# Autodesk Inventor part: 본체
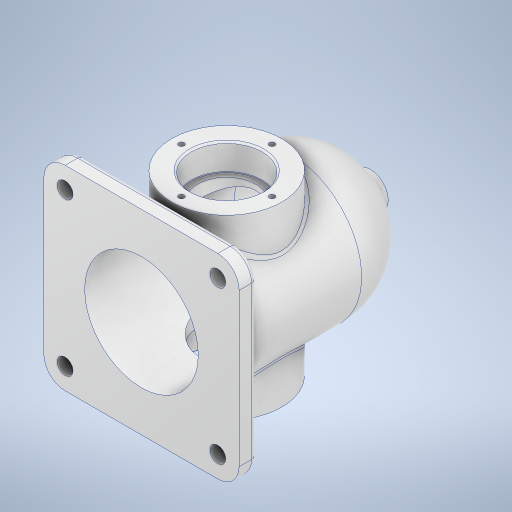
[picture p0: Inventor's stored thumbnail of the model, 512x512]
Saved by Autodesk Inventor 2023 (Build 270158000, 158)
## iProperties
Created: 2025-04
Part Number: 본체
Material: 알루미늄 6061
Document SubType Name: Modeling
Designer: ADMIN_PC
Density: 2.7 g/cm^3
Appearance: 알루미늄 - 평지
Mass: 865.906 g
Surface Area: 800.755 cm^2
Volume: 320.706 cm^3
Author: ADMIN_PC
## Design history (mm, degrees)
sketch "스케치1"
  geometry: L1 (-55, -55)-(55, -55); L2 (55, -55)-(55, 55); L3 (55, 55)-(-55, 55); L4 (-55, 55)-(-55, -55); L5 (-55, -55)-(55, 55); L6 (55, -55)-(-55, 55); 1 further point
  constraints: 12 end point, 2 midpoint, 2 parallel, 1 horizontal, 1 perpendicular
  dimensions: "d0" = 110 distance of L2.end L3.end; "d1" = 110 distance of L1.end L2.end
extrude "돌출1" new body sketch "스케치1" distance "d2" = 10; taper "d3" = 0 deg
fillet "모깎기1" dims "d4" = 12
sketch "스케치2"
  geometry: C1 r 40 at (0, 0); 1 further point
  constraints: 1 centre point, 1 coincident
  dimensions: "d5" = 80 diameter of C1
extrude "돌출2" join sketch "스케치2" distance "d6" = 74; taper "d7" = 0 deg
sketch "스케치3"
  geometry: L1 (-40, -74)-(40, -74) reference; L2 (0, -138.8)-(0, 34.8) reference; A1 r 40 centre (0, -74) between (-40, -74) and (0, -114); 2 further points
  constraints: 2 end point, 2 point on circle, 1 centre point, 1 midpoint, 1 point on line
revolve "회전1" sketch "스케치3" stored, may be unused: angle "d9" = 90 deg
sketch "스케치4"
  geometry: C1 r 32 at (0, 0); 1 further point
  constraints: 1 centre point, 1 coincident
  dimensions: "d10" = 64 diameter of C1
extrude "돌출3" cut sketch "스케치4" distance "d11" = 84; taper "d12" = 0 deg
sketch "스케치5"
  geometry: L1 (-32, -74)-(32, -74) reference; L2 (0, -138.8)-(0, 34.8) reference; A1 r 32 centre (0, -74) between (-32, -74) and (0, -106); 2 further points
  constraints: 2 point on circle, 1 centre point, 1 end point, 1 midpoint, 1 point on line
revolve "회전2" sketch "스케치5" stored, may be unused: angle "d13" = 90 deg
node "작업 평면2"
sketch "스케치6"
  geometry: L1 (-43, 10)-(43, 10) reference; L2 (0, 10)-(0, -38); C1 r 31 at (0, -38); 1 further point
  constraints: 2 end point, 1 centre point, 1 coincident, 1 midpoint, 1 vertical
  dimensions: "d15" = 48 distance of L2.start L2.end; "d16" = 62 diameter of C1
extrude "돌출4" join sketch "스케치6" stored distance "d17" = 84; taper "d18" = 0 deg
sketch "스케치7"
  geometry: C1 r 20 at (0, 0); 1 further point
  constraints: 1 centre point
  dimensions: "d19" = 40 diameter of C1
extrude "돌출5" cut sketch "스케치7" distance "d20" = 15; taper "d21" = 0 deg
sketch "스케치8"
  geometry: C1 r 16.5 at (0, 0); 1 further point
  constraints: 1 centre point
  dimensions: "d22" = 33 diameter of C1
extrude "돌출6" cut sketch "스케치8" extent not by distance; stored distance "d23" = 0; taper "d24" = 0 deg
sketch "스케치9"
  geometry: L1 (-43, -43)-(43, -43); L2 (43, -43)-(43, 43); L3 (43, 43)-(-43, 43); L4 (-43, 43)-(-43, -43); L5 (-43, -43)-(43, 43); L6 (43, -43)-(-43, 43); 5 further points
  constraints: 12 end point, 4 coincident, 2 midpoint, 2 parallel, 1 horizontal, 1 perpendicular
  dimensions: "d25" = 86 distance of L2.end L3.end; "d26" = 86 distance of L1.end L2.end
hole "구멍1" sketch "스케치9" at (-43, 43), (-43, -43), (43, -43), (43, 43) diameter "d27" = 9; stored, may be unused: countersink angle "d31" = 90 deg, drill point angle "d33" = 0 deg; dims "d28" = 12, "d29" = 4, "d30" = 2, "d32" = 17.1
sketch "스케치10" dims "d34" = 51
  geometry: L1 (0, 100.8)-(0, -72.8) reference; 3 further points
  constraints: 1 point on line, 1 vertical alignment, 2 other
hole "구멍2" sketch "스케치10" at (0, 25.5) diameter "d35" = 3.242; stored, may be unused: countersink angle "d39" = 90 deg, drill point angle "d41" = 118 deg; dims "d36" = 8, "d37" = 4, "d38" = 2, "d40" = 10
node "작업 평면3"
sketch "스케치11"
  geometry: C1 r 10 at (0, 0); 1 further point
  constraints: 1 centre point, 1 coincident
  dimensions: "d46" = 20 diameter of C1
extrude "돌출7" join sketch "스케치11" stored distance "d47" = 10; taper "d48" = 0 deg
sketch "스케치12"
  geometry: 2 further points
  constraints: 1 coincident
hole "구멍3" sketch "스케치12" at (0, 0) diameter "d49" = 5.1881; stored, may be unused: countersink angle "d53" = 90 deg, drill point angle "d55" = 0 deg; dims "d50" = 12, "d51" = 4, "d52" = 2, "d54" = 16
chamfer "모따기1" distance "d56" = 1; stored, may be unused: second distance "d57" = 2, angle "d58" = 45 deg
fillet "모깎기2" dims "d59" = 0.3
fillet "모깎기3" dims "d60" = 3
fillet "모깎기4" dims "d61" = 3
node "작업 평면4"
sketch "스케치13"
  geometry: L1 (-43, 10)-(43, 10) reference; L2 (-50, -7)-(-50, -69) reference; 2 further points
  constraints: 1 other
  dimensions: "d63" = 30 distance from line of L1 point (0, -20); "d64" = 50 distance from line of L2 point (0, -20)
feature "엠보싱1" sketch "스케치13" dims "d0" = 110, "d1" = 110, "d65" = 0.5, "d66" = 0
fillet "모깎기5" dims "d67" = 3
fillet "모깎기6" dims "d68" = 3
node "솔리드1"
mirror "미러1"
mirror "미러2"
pattern_circular "원형 패턴1" dims angle "d43" = 360 deg
mirror "미러3"
feature "A9D066F2-1C7D-4E18-AEED-F7BC21143FA4" dims "d27" = 9, "d28" = 12, "d29" = 4, "d30" = 2, "d31" = 90 deg, "d32" = 17.1, "d33" = 0
other parameters: "d45" = -119
